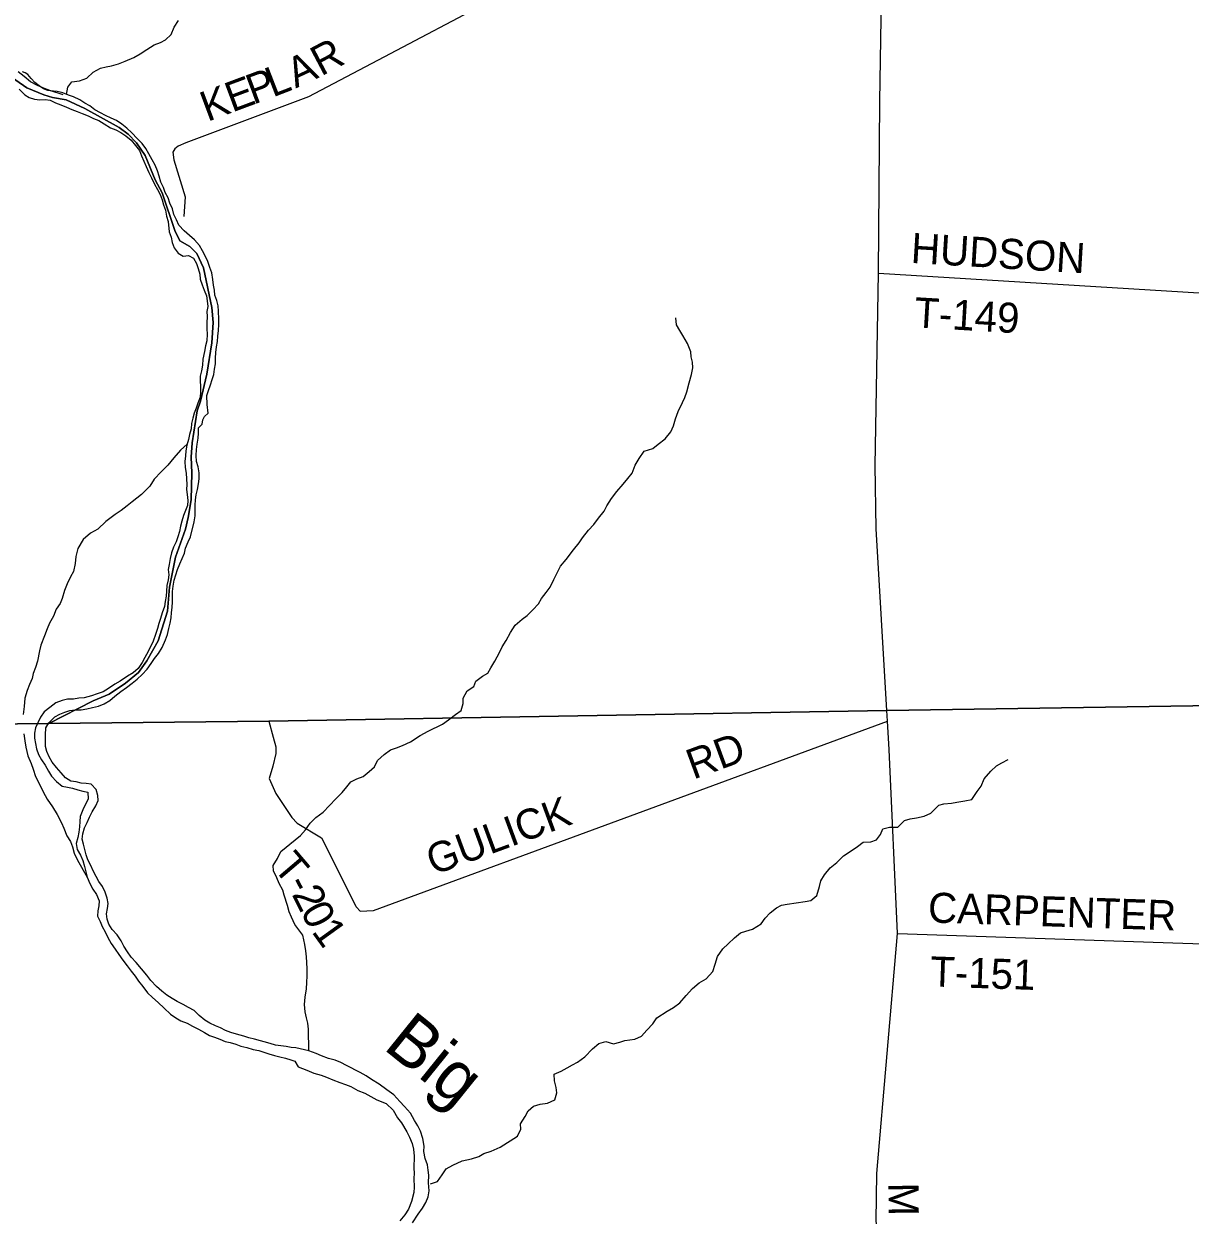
# Model space of a CAD drawing. Extents: x 1643459 to 2064572, y 425441 to 780708.
# Drawn here: x 1790021 to 1801650, y 626838 to 638720 of the extents above; entities that cross this region are included whole.
import ezdxf

# ---------------------------------------------------------------- set-up
doc = ezdxf.new("R2010")
doc.units = 0
for name, color, linetype in [('GM_X_City_Street', 7, 'Continuous'), ('GM_X_Major_River', 7, 'Continuous'), ('GM_X_Major_River_Text', 7, 'Continuous'), ('GM_X_Minor_Lake', 7, 'Continuous'), ('GM_X_Section_Text', 7, 'Continuous'), ('GM_X_State_Shield', 7, 'Continuous'), ('GM_X_Unincorporated_Text', 7, 'Continuous'), ('GM_X_US_Route', 7, 'Continuous')]:
    doc.layers.add(name, color=color, linetype=linetype)

msp = doc.modelspace()

# ---------------------------------------------------------------- linework, layer by layer
at = {"layer": 'GM_X_City_Street'}
for points in [[(1789787, 638265), (1790052, 638082), (1790221, 638013), (1790308, 637984), (1790444, 637963), (1790628, 637874), (1790971, 637685), (1791062, 637620), (1791145, 637534), (1791231, 637407), (1791331, 637164), (1791399, 637034), (1791527, 636658), (1791577, 636557), (1791677, 636499), (1791745, 636430), (1791813, 636286), (1791897, 635892), (1791909, 635741), (1791896, 635537), (1791847, 635225), (1791782, 634957), (1791751, 634861), (1791699, 634542), (1791690, 634397), (1791697, 634242), (1791689, 633972), (1791660, 633796), (1791634, 633679), (1791533, 633402), (1791472, 633102), (1791454, 632863), (1791359, 632567), (1791246, 632366), (1791164, 632252), (1791036, 632144), (1790873, 632034), (1790714, 631969), (1790269, 631741), (1788081, 631718)], [(1804074, 631955), (1798625, 631871), (1792463, 631765), (1790269, 631741), (1790714, 631969), (1790873, 632034), (1791036, 632144), (1791164, 632252), (1791246, 632366), (1791359, 632567), (1791454, 632863), (1791472, 633102), (1791533, 633402), (1791634, 633679), (1791660, 633796), (1791689, 633972), (1791697, 634242), (1791690, 634397), (1791699, 634542), (1791751, 634861), (1791782, 634957), (1791847, 635225), (1791896, 635537), (1791909, 635741), (1791897, 635892), (1791813, 636286), (1791745, 636430), (1791677, 636499), (1791577, 636557), (1791527, 636658), (1791399, 637034), (1791331, 637164), (1791231, 637407), (1791145, 637534), (1791062, 637620), (1790971, 637685), (1790628, 637874), (1790444, 637963), (1790308, 637984), (1790221, 638013), (1790052, 638082), (1789787, 638265)], [(1788081, 631718), (1790269, 631741), (1792463, 631765), (1798625, 631871), (1804074, 631955), (1804758, 629443), (1806186, 624205), (1806771, 622059), (1808540, 616123), (1810366, 609995), (1807901, 608849), (1807239, 608541), (1800646, 605476), (1795084, 602890), (1793558, 602184), (1791118, 601055), (1790575, 602316), (1789055, 605851)]]:
    msp.add_lwpolyline(points, dxfattribs=at)
at = {"layer": 'GM_X_Major_River_Text'}
for points in [[(1798853, 639986), (1798040, 640052), (1797110, 639744), (1795980, 639480), (1795638, 639406), (1795515, 639396), (1793674, 638421), (1793674, 638421)], [(1793674, 638421), (1792860, 637990), (1791638, 637534), (1791559, 637500), (1791527, 637472), (1791507, 637440), (1791518, 637364), (1791629, 636994), (1791616, 636798)], [(1798542, 636232), (1805369, 635815)], [(1792463, 631765), (1792508, 631605), (1792535, 631510), (1792533, 631444), (1792504, 631316), (1792466, 631194), (1792535, 631045), (1792694, 630803), (1792748, 630749), (1792988, 630602), (1793332, 629919), (1793335, 629913)], [(1793335, 629913), (1793337, 629909), (1793375, 629869), (1793507, 629878), (1798632, 631764)], [(1798731, 629647), (1804421, 629454)]]:
    msp.add_lwpolyline(points, dxfattribs=at)
at = {"layer": 'GM_X_Minor_Lake'}
for points in [[(1798632, 631764), (1798625, 631871), (1798519, 633684), (1798508, 634315), (1798542, 636232), (1798557, 637947), (1798574, 638978), (1798853, 639986), (1799682, 642973)], [(1798992, 621769), (1798784, 624124), (1798680, 625266), (1798573, 626321), (1798521, 626782), (1798525, 627255), (1798731, 629647), (1798648, 631482), (1798632, 631764)]]:
    msp.add_lwpolyline(points, dxfattribs=at)
at = {"layer": 'GM_X_Unincorporated_Text'}
for points in [[(1790409, 638031), (1790383, 638039), (1790353, 638045), (1790285, 638050), (1790259, 638055), (1790217, 638071), (1790173, 638100), (1790132, 638136), (1790094, 638173), (1790060, 638215), (1790035, 638232), (1790007, 638242)], [(1789973, 638068), (1790030, 638010)], [(1791489, 632794), (1791493, 632848), (1791501, 632899), (1791503, 632955), (1791503, 633007), (1791505, 633057), (1791509, 633113), (1791519, 633172), (1791537, 633224), (1791553, 633276), (1791578, 633334), (1791600, 633386), (1791624, 633441), (1791634, 633491), (1791660, 633553), (1791684, 633603), (1791720, 633754), (1791728, 633814), (1791730, 633864), (1791730, 633918), (1791734, 633971), (1791740, 634021), (1791752, 634077), (1791762, 634131), (1791768, 634183), (1791768, 634242), (1791758, 634302), (1791744, 634356), (1791740, 634414), (1791742, 634476), (1791750, 634529), (1791758, 634587), (1791762, 634637), (1791764, 634691), (1791798, 634726), (1791806, 634769), (1791824, 634803), (1791858, 634837), (1791849, 634923), (1791847, 635012), (1791861, 635063), (1791883, 635119), (1791899, 635171), (1791915, 635221), (1791923, 635275), (1791933, 635328), (1791933, 635386), (1791937, 635442), (1791943, 635498), (1791951, 635552), (1791957, 635605), (1791963, 635661), (1791967, 635721), (1791965, 635773), (1791963, 635855), (1791959, 635906), (1791945, 635962), (1791927, 636012), (1791923, 636064), (1791913, 636114), (1791905, 636169), (1791897, 636235), (1791877, 636291), (1791855, 636351), (1791829, 636405), (1791802, 636456), (1791774, 636510), (1791724, 636566), (1791672, 636608), (1791620, 636656), (1791567, 636711), (1791543, 636765), (1791517, 636819), (1791505, 636875), (1791477, 636931), (1791459, 636984), (1791429, 637038), (1791413, 637088), (1791387, 637142), (1791371, 637200), (1791353, 637255), (1791331, 637309), (1791302, 637363), (1791268, 637423), (1791236, 637475), (1791200, 637526), (1791152, 637576), (1791098, 637634), (1791048, 637680), (1790997, 637718), (1790945, 637754), (1790893, 637780), (1790837, 637807), (1790784, 637831), (1790730, 637863), (1790680, 637901), (1790628, 637929), (1790578, 637963), (1790517, 637991), (1790467, 638008), (1790409, 638031)], [(1790030, 638010), (1790074, 637985), (1790126, 637969), (1790180, 637961), (1790234, 637965), (1790285, 637957), (1790337, 637933), (1790391, 637913), (1790447, 637887), (1790499, 637865), (1790552, 637845), (1790602, 637827), (1790664, 637801), (1790716, 637774), (1790770, 637756), (1790821, 637722), (1790885, 637684), (1790937, 637662), (1790989, 637636), (1791039, 637604), (1791092, 637558), (1791134, 637505), (1791176, 637455), (1791194, 637403), (1791218, 637349), (1791240, 637297), (1791268, 637238), (1791294, 637184), (1791323, 637122), (1791355, 637068), (1791381, 637018), (1791399, 636964), (1791415, 636913), (1791433, 636861), (1791445, 636803), (1791459, 636749), (1791471, 636644), (1791489, 636592), (1791501, 636540), (1791521, 636484), (1791559, 636434), (1791610, 636403), (1791662, 636409), (1791712, 636383), (1791742, 636331), (1791758, 636279), (1791776, 636223), (1791780, 636173), (1791800, 636116), (1791818, 636062), (1791841, 636008), (1791849, 635956), (1791855, 635902), (1791847, 635851), (1791849, 635801), (1791847, 635737), (1791845, 635679), (1791849, 635625), (1791845, 635558), (1791833, 635508), (1791824, 635452), (1791806, 635376), (1791802, 635314), (1791792, 635259), (1791778, 635207), (1791780, 635157), (1791784, 635105), (1791782, 635051), (1791778, 634996), (1791756, 634938), (1791738, 634888), (1791720, 634836), (1791706, 634786), (1791694, 634735), (1791690, 634681), (1791674, 634625), (1791662, 634573), (1791646, 634519), (1791638, 634462), (1791632, 634412), (1791628, 634354), (1791630, 634296), (1791640, 634240), (1791642, 634183), (1791646, 634125), (1791642, 634075), (1791650, 634025), (1791656, 633967), (1791652, 633916), (1791634, 633866), (1791614, 633816), (1791596, 633760), (1791584, 633710), (1791572, 633655), (1791555, 633605), (1791541, 633553), (1791515, 633499), (1791495, 633445), (1791481, 633386), (1791469, 633326), (1791461, 633276)], [(1791461, 633276), (1791467, 633224), (1791459, 633174), (1791447, 633117), (1791443, 633063), (1791439, 633013), (1791431, 632959), (1791423, 632907), (1791399, 632846), (1791383, 632788), (1791367, 632738), (1791353, 632688), (1791335, 632630), (1791311, 632563), (1791262, 632459), (1791226, 632399), (1791202, 632349), (1791160, 632290), (1791110, 632248), (1791056, 632214), (1790981, 632164), (1790929, 632134), (1790865, 632092), (1790813, 632058), (1790752, 632036), (1790696, 632017), (1790624, 631997), (1790570, 631993), (1790516, 631985), (1790455, 631983), (1790403, 631971), (1790339, 631947), (1790279, 631903), (1790224, 631857), (1790188, 631805), (1790162, 631750), (1790138, 631698), (1790128, 631646), (1790128, 631596), (1790138, 631542), (1790146, 631490), (1790166, 631433), (1790196, 631381), (1790234, 631327), (1790267, 631265), (1790297, 631215), (1790347, 631164), (1790405, 631118), (1790457, 631106), (1790507, 631096), (1790558, 631080), (1790610, 631066), (1790660, 631058), (1790664, 630988), (1790636, 630936), (1790610, 630881), (1790582, 630815), (1790578, 630765), (1790576, 630711), (1790568, 630658), (1790558, 630604), (1790544, 630544), (1790552, 630486), (1790586, 630430), (1790610, 630375), (1790626, 630315), (1790638, 630263), (1790652, 630209), (1790680, 630145), (1790710, 630088), (1790746, 630036), (1790771, 629974), (1790768, 629924), (1790758, 629874), (1790756, 629821), (1790783, 629767), (1790803, 629717), (1790831, 629665), (1790859, 629607), (1790891, 629548), (1790931, 629490), (1790967, 629438), (1791009, 629380), (1791050, 629324), (1791092, 629273), (1791130, 629221), (1791164, 629171), (1791208, 629119), (1791254, 629057), (1791305, 629008), (1791361, 628960), (1791419, 628902), (1791483, 628844), (1791535, 628808), (1791588, 628776), (1791648, 628752), (1791702, 628723), (1791762, 628695), (1791821, 628659), (1791873, 628631), (1791923, 628615)], [(1792582, 628527), (1792530, 628535), (1792478, 628549), (1792320, 628593), (1792264, 628607), (1792214, 628625), (1792142, 628643), (1792084, 628659), (1792033, 628681), (1791983, 628707), (1791931, 628727), (1791875, 628752), (1791825, 628782), (1791768, 628830), (1791718, 628878), (1791662, 628908), (1791610, 628938), (1791551, 628968), (1791499, 628998), (1791447, 629033), (1791397, 629073), (1791343, 629119), (1791288, 629179), (1791248, 629231), (1791194, 629296), (1791140, 629358), (1791092, 629412), (1791054, 629466), (1791019, 629520), (1790991, 629575), (1790951, 629633), (1790903, 629687), (1790867, 629739), (1790851, 629789), (1790845, 629844), (1790855, 629896), (1790861, 629948), (1790851, 630000), (1790831, 630060), (1790805, 630115), (1790768, 630167), (1790742, 630217), (1790714, 630271), (1790688, 630327), (1790660, 630382), (1790642, 630432), (1790628, 630484), (1790616, 630538), (1790604, 630588), (1790608, 630642), (1790626, 630701), (1790654, 630753), (1790676, 630807), (1790702, 630861), (1790738, 630921), (1790762, 630974), (1790758, 631024), (1790744, 631082), (1790694, 631136), (1790642, 631144), (1790592, 631146), (1790542, 631160), (1790491, 631168), (1790437, 631200), (1790395, 631251), (1790347, 631303), (1790305, 631357), (1790275, 631409), (1790250, 631461), (1790238, 631514), (1790236, 631564), (1790236, 631630), (1790242, 631698), (1790271, 631748), (1790329, 631809), (1790379, 631835), (1790429, 631855), (1790481, 631871), (1790534, 631879), (1790594, 631879), (1790650, 631887), (1790706, 631901), (1790766, 631915), (1790823, 631939), (1790877, 631971), (1790929, 632013), (1790989, 632060), (1791044, 632100), (1791100, 632144), (1791150, 632184), (1791200, 632232), (1791250, 632284), (1791290, 632341), (1791323, 632391), (1791365, 632441), (1791401, 632499), (1791433, 632576), (1791453, 632628), (1791467, 632690), (1791481, 632744), (1791489, 632794)], [(1791923, 628615), (1791977, 628593), (1792027, 628569), (1792080, 628561), (1792136, 628545), (1792186, 628525), (1792246, 628509), (1792308, 628491), (1792363, 628479), (1792413, 628463), (1792465, 628446), (1792519, 628430), (1792572, 628418), (1792630, 628404), (1792682, 628388), (1792722, 628374)], [(1792732, 628507), (1792688, 628509), (1792636, 628519), (1792582, 628527)], [(1793896, 626763), (1793953, 626849), (1793996, 626908), (1794028, 626966), (1794053, 627022), (1794064, 627082), (1794057, 627162), (1794058, 627236), (1794051, 627286), (1794045, 627341), (1794024, 627403), (1794009, 627473), (1794012, 627525), (1794000, 627602), (1793975, 627676), (1793948, 627729), (1793917, 627781), (1793876, 627854), (1793816, 627921), (1793769, 627973), (1793710, 628038), (1793642, 628087), (1793565, 628144), (1793487, 628193), (1793434, 628228), (1793374, 628261), (1793239, 628331), (1793181, 628362), (1793124, 628384), (1793060, 628401), (1792990, 628426), (1792936, 628451), (1792864, 628478), (1792732, 628507)], [(1792722, 628374), (1792756, 628319), (1792844, 628284), (1792912, 628253), (1792987, 628236), (1793039, 628213), (1793101, 628188), (1793171, 628161), (1793227, 628142), (1793282, 628122), (1793352, 628081), (1793422, 628054), (1793481, 628021), (1793541, 627990), (1793633, 627951), (1793702, 627884), (1793747, 627809), (1793788, 627759), (1793841, 627670), (1793865, 627617), (1793894, 627553), (1793905, 627495), (1793912, 627426), (1793911, 627308), (1793912, 627258), (1793911, 627204), (1793914, 627116), (1793908, 627066), (1793888, 626976), (1793855, 626898), (1793819, 626842), (1793770, 626783)]]:
    msp.add_lwpolyline(points, dxfattribs=at)
at = {"layer": 'GM_X_US_Route'}
for points in [[(1790447, 638016), (1790459, 638088), (1790500, 638142), (1790576, 638150), (1790648, 638177), (1790712, 638237), (1790787, 638277), (1790843, 638291), (1790895, 638300), (1790965, 638322), (1791033, 638348), (1791117, 638385), (1791180, 638421), (1791248, 638465), (1791322, 638510), (1791384, 638534), (1791435, 638560), (1791491, 638614), (1791519, 638686), (1791562, 638754)], [(1790412, 638012), (1790280, 638056), (1790210, 638080), (1790156, 638105), (1790088, 638141), (1790023, 638196), (1789963, 638242)], [(1792780, 630624), (1792829, 630681), (1792875, 630747), (1792934, 630804), (1793005, 630859), (1793070, 630925), (1793133, 630990), (1793196, 631053), (1793243, 631109), (1793281, 631161), (1793342, 631190), (1793406, 631213), (1793465, 631263), (1793517, 631310), (1793548, 631372), (1793613, 631431), (1793678, 631480), (1793736, 631500), (1793796, 631523), (1793875, 631558), (1793974, 631623), (1794053, 631666), (1794194, 631735), (1794254, 631778), (1794325, 631831), (1794380, 631873), (1794400, 631941), (1794403, 631995), (1794440, 632068), (1794507, 632110), (1794527, 632164), (1794594, 632213), (1794647, 632244), (1794679, 632296), (1794716, 632362), (1794763, 632449), (1794792, 632507), (1794829, 632571), (1794874, 632648), (1794919, 632722), (1794990, 632781), (1795040, 632819), (1795097, 632874), (1795154, 632936), (1795181, 632989), (1795230, 633049), (1795270, 633100), (1795307, 633178), (1795342, 633250), (1795373, 633312), (1795430, 633379), (1795501, 633474), (1795558, 633542), (1795593, 633594), (1795652, 633669), (1795705, 633727), (1795752, 633788), (1795807, 633860), (1795835, 633913), (1795882, 633985), (1795935, 634054), (1795998, 634130), (1796045, 634185), (1796086, 634239), (1796117, 634317), (1796156, 634386), (1796205, 634458), (1796291, 634485), (1796346, 634526), (1796415, 634582), (1796472, 634651), (1796498, 634711), (1796517, 634781), (1796544, 634855), (1796589, 634942), (1796612, 634994), (1796633, 635050), (1796656, 635138), (1796677, 635222), (1796692, 635288), (1796687, 635346), (1796675, 635398), (1796670, 635450), (1796637, 635531), (1796592, 635610), (1796563, 635660), (1796527, 635719), (1796522, 635787)], [(1791649, 634526), (1791583, 634468), (1791516, 634390), (1791457, 634318), (1791389, 634253), (1791322, 634177), (1791276, 634109), (1791195, 634027), (1791102, 633951), (1791052, 633913), (1790993, 633867), (1790933, 633827), (1790840, 633756), (1790759, 633680), (1790687, 633640), (1790612, 633576), (1790559, 633486), (1790541, 633408), (1790534, 633338), (1790516, 633258), (1790487, 633204), (1790453, 633135), (1790428, 633067), (1790405, 632989), (1790385, 632937), (1790345, 632881), (1790316, 632813), (1790277, 632741), (1790253, 632687), (1790228, 632617), (1790192, 632523), (1790179, 632466), (1790156, 632362), (1790136, 632300), (1790115, 632242), (1790103, 632190), (1790077, 632132), (1790054, 632072), (1790031, 631993), (1790025, 631911), (1790016, 631833)], [(1790021, 631638), (1790032, 631570), (1790042, 631506), (1790061, 631419), (1790093, 631343), (1790115, 631288), (1790138, 631212), (1790166, 631156), (1790215, 631059), (1790255, 630988), (1790307, 630912), (1790352, 630835), (1790396, 630751), (1790421, 630699), (1790451, 630622), (1790487, 630566), (1790506, 630513), (1790524, 630447), (1790555, 630379), (1790652, 630209)], [(1794077, 627150), (1794147, 627173), (1794192, 627240), (1794233, 627302), (1794299, 627337), (1794392, 627380), (1794486, 627399), (1794557, 627422), (1794607, 627452), (1794682, 627477), (1794770, 627518), (1794942, 627626), (1794977, 627696), (1794973, 627748), (1795020, 627822), (1795049, 627879), (1795102, 627927), (1795170, 627946), (1795242, 627957), (1795315, 627990), (1795334, 628058), (1795329, 628112), (1795313, 628177), (1795310, 628243), (1795379, 628276), (1795439, 628308), (1795490, 628339), (1795542, 628364), (1795615, 628418), (1795690, 628497), (1795755, 628550), (1795825, 628569), (1795901, 628548), (1795963, 628564), (1796015, 628581), (1796114, 628594), (1796180, 628625), (1796233, 628683), (1796294, 628748), (1796333, 628806), (1796436, 628874), (1796498, 628910), (1796561, 628955), (1796626, 629028), (1796687, 629100), (1796754, 629155), (1796824, 629196), (1796891, 629270), (1796914, 629342), (1796939, 629418), (1796990, 629493), (1797043, 629545), (1797108, 629604), (1797168, 629655), (1797219, 629671), (1797287, 629690), (1797374, 629745), (1797412, 629799), (1797463, 629854), (1797526, 629903), (1797576, 629929), (1797631, 629940), (1797723, 629953), (1797811, 629966), (1797867, 629975), (1797928, 630027), (1797953, 630117), (1797966, 630173), (1798003, 630232), (1798062, 630302), (1798128, 630355), (1798193, 630422), (1798280, 630479), (1798333, 630515), (1798391, 630558), (1798465, 630561), (1798522, 630581), (1798562, 630634), (1798587, 630692), (1798652, 630709), (1798736, 630708), (1798803, 630776), (1798857, 630791), (1798923, 630802), (1798999, 630817), (1799066, 630846), (1799143, 630928), (1799193, 630941), (1799271, 630946), (1799325, 630956), (1799402, 630971), (1799472, 630984), (1799527, 631063), (1799566, 631117), (1799597, 631191), (1799664, 631266), (1799719, 631320), (1799771, 631351), (1799834, 631384)], [(1792722, 629737), (1792689, 629811), (1792667, 629865), (1792649, 629928), (1792616, 630030), (1792602, 630080), (1792567, 630147), (1792545, 630201), (1792512, 630274), (1792508, 630324), (1792551, 630396), (1792585, 630466), (1792780, 630624)], [(1792681, 630555), (1792680, 630554)], [(1792864, 628478), (1792861, 628692), (1792852, 628752), (1792841, 628805), (1792825, 628865), (1792818, 628939), (1792825, 629013), (1792838, 629097), (1792843, 629160), (1792846, 629224), (1792847, 629296), (1792844, 629358), (1792838, 629414), (1792833, 629476), (1792822, 629539), (1792803, 629631), (1792722, 629737)]]:
    msp.add_lwpolyline(points, dxfattribs=at)

# ---------------------------------------------------------------- texts
at = {"layer": 'GM_X_Major_River'}
for s, rotation, p in [('R', 27.8736, (1792985, 638193)), ('A', 24.9868, (1792731, 638074)), ('L', 21.1791, (1792502, 637984)), ('E', 20.4397, (1792098, 637834)), ('P', 20.4397, (1792308, 637912)), ('K', 20.4443, (1791851, 637741)), ('HUDSON', 356.5368, (1798860, 636336)), ('T-149', 356.6332, (1798893, 635694)), ('RD', 20.1502, (1796696, 631181)), ('GULICK', 20.216, (1794104, 630226)), ('T', 310.3796, (1792497, 630303)), ('-', 297.6997, (1792632, 630147)), ('2', 296.7466, (1792689, 630039)), ('0', 297.6514, (1792774, 629869)), ('CARPENTER', 358.1145, (1799033, 629758)), ('1', 305.7475, (1792884, 629666)), ('T-151', 358.0347, (1799055, 629120))]:
    msp.add_text(s, height=300, rotation=rotation, dxfattribs=at).set_placement(p)
at = {"layer": 'GM_X_Section_Text'}
msp.add_text('M', height=300, rotation=270.7414, dxfattribs=at).set_placement((1798641, 627162))
at = {"layer": 'GM_X_State_Shield'}
msp.add_text('Big', height=500, rotation=321.1165, dxfattribs=at).set_placement((1793593, 628504))

doc.saveas('drawing.dxf')
